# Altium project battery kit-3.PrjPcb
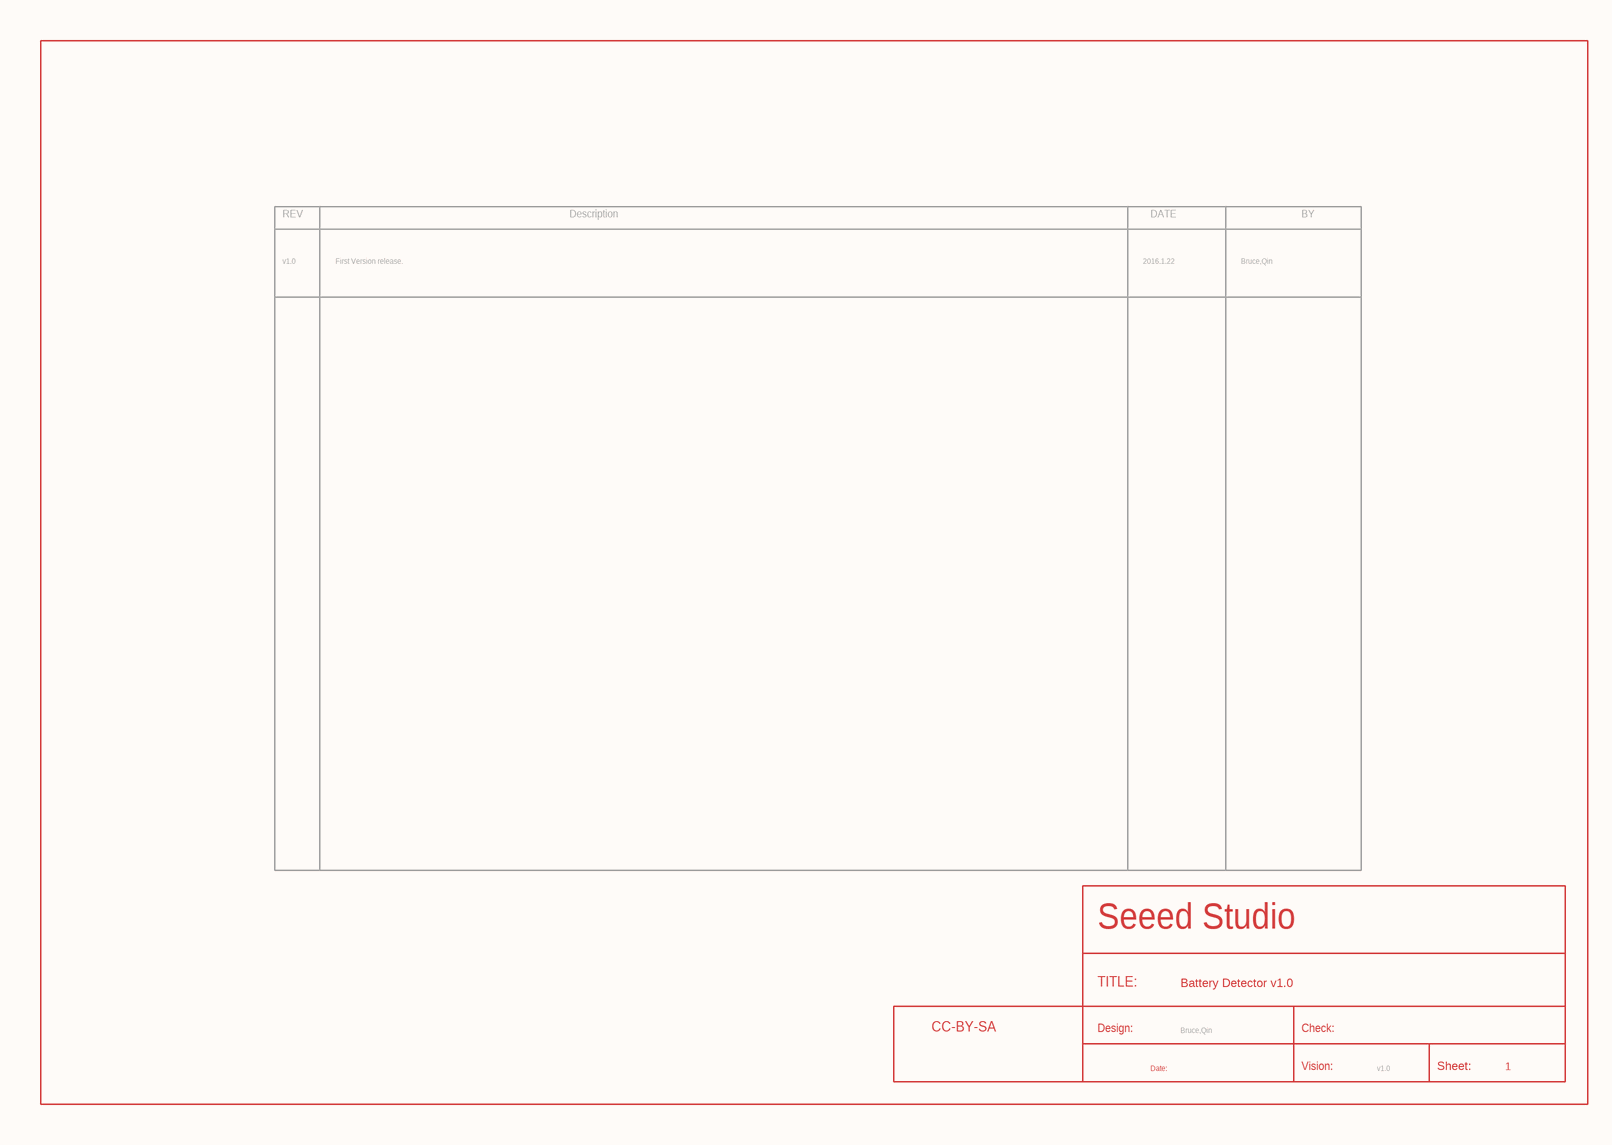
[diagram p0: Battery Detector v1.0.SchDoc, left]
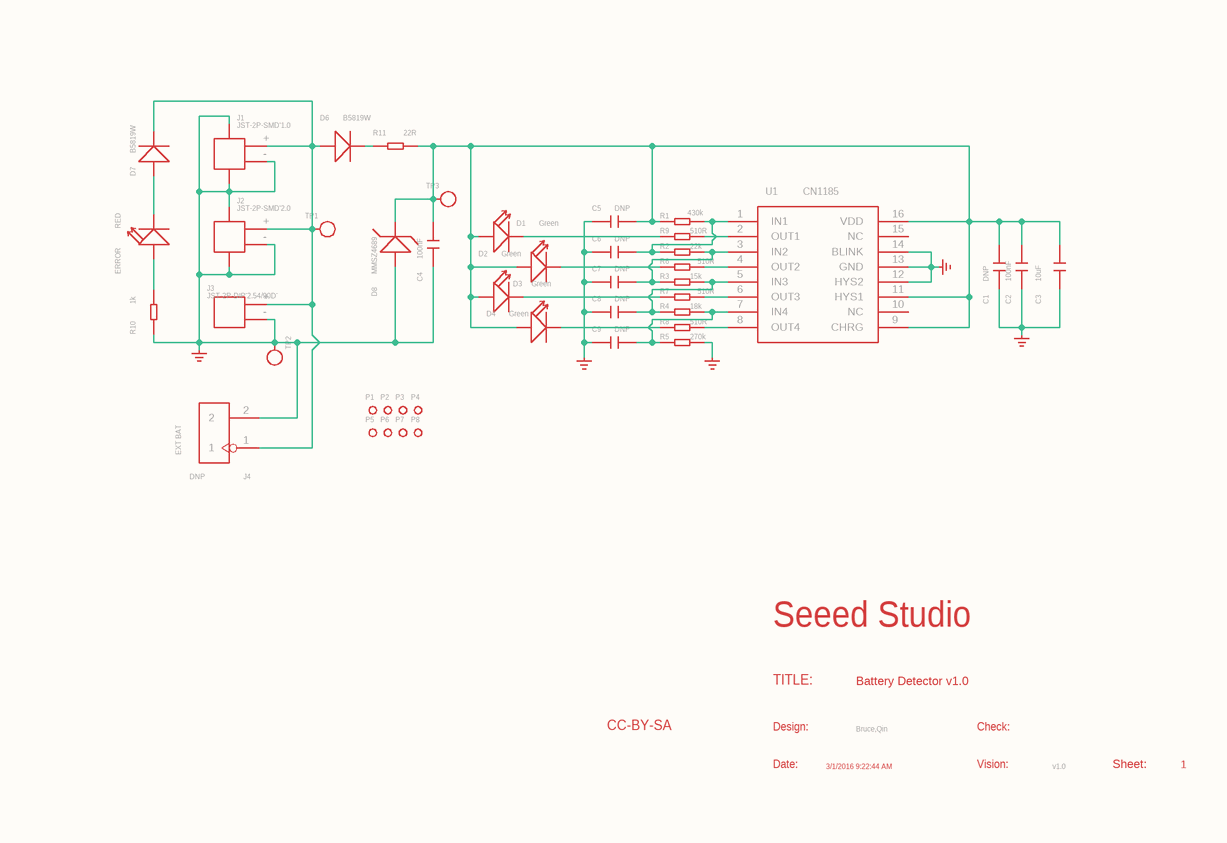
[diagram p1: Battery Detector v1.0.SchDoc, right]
1 sheet, 51 parts. Net scope: global (net labels, ports and power ports of the same name join across sheets).
Board file: Battery Detector v1.0.PcbDoc

## Sheet Battery Detector v1.0.SchDoc: Battery Detector v1.0
size 545 x 197 mm; Date: 3/1/2016 9:22:44 AM; SheetNumber: 1; Origin: Eagle; GateName_1: G$1; SymbolName_1: SEEEDSTUDIO-OPEN-SCH-FRAME; LibraryName: moudle-new; DeviceSetName: SEEEDSTUDIO-OPEN-SCH-FRAME; Sheet: Sheet:; SeeedStudio: Seeed Studio; Design: Design:; Check: Check:; Vision: Vision:; CC-BY-SA: CC-BY-SA

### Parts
C1  DNP  [C0603]
C2  100nF  [C0603]
C3  10uF  [C0805]
C4  100nF  [C0603]
C5  DNP  [C0603]
C6  DNP  [C0603]
C7  DNP  [C0603]
C8  DNP  [C0603]
C9  DNP  [C0603]
D1  Green  [LED-0603]
D2  Green  [LED-0603]
D3  Green  [LED-0603]
D4  Green  [LED-0603]
D6  B5819W  [SOD-123]
D7  B5819W  [SOD-123]
D8  MMSZ4689  [SOD-123]
ERROR  RED  [LED-0603]
FR2  DRAWING_NAME: Battery Detector v1.0  SHEET: 1  Sheet: Sheet:  SeeedStudio: Seeed Studio  TITLE: TITLE:  Design: Design:  Check: Check:  Vision: Vision:  Date: Date:  [SEEEDSTUDIO-PCB-FRAME]  (hidden comment: SEEEDSTUDIO-OPEN-SCH-FRAME)
J1  JST-2P-SMD'1.0  [HW2-SMD-1.0-90D]
J2  JST-2P-SMD'2.0  [HW2-SMD-2.0-90D]
J3  JST-2P-DIP'2.54/90D'  [JST2-2.54-90D]
J4  DNP  [H2-2.54]
P1  MARK-1.0'ANNULAR'  [ROUND-MARK-1.0]  (value not drawn)
P2  MARK-1.0'ANNULAR'  [ROUND-MARK-1.0]  (value not drawn)
P3  MARK-1.0'ANNULAR'  [ROUND-MARK-1.0]  (value not drawn)
P4  MARK-1.0'ANNULAR'  [ROUND-MARK-1.0]  (value not drawn)
P5  MARK-1.0'ANNULAR'  [ROUND-MARK-1.0]  (value not drawn)
P6  MARK-1.0'ANNULAR'  [ROUND-MARK-1.0]  (value not drawn)
P7  MARK-1.0'ANNULAR'  [ROUND-MARK-1.0]  (value not drawn)
P8  MARK-1.0'ANNULAR'  [ROUND-MARK-1.0]  (value not drawn)
R1  430k  [R0603]
R2  22k  [R0603]
R3  15k  [R0603]
R4  18k  [R0603]
R5  270k  [R0603]
R6  510R  [R0603]
R7  510R  [R0603]
R8  510R  [R0603]
R9  510R  [R0603]
R10  1k  [R0603]
R11  22R  [R0805]
TP1  DNP  [TP-D45MIL]  (value not drawn)
TP2  DNP  [TP-D45MIL]  (value not drawn)
TP3  DNP  [TP-D45MIL]  (value not drawn)
U1  CN1185  [TSSOP16-0.65-5X4.4MM]
U$1  SEEEDSTUDIO-SCH-MODLIST  (value not drawn)
U$2  GND_POWER  (value not drawn)
U$3  GND_POWER  (value not drawn)
U$4  GND_POWER  (value not drawn)
U$5  GND_POWER  (value not drawn)
U$6  GND_POWER  (value not drawn)

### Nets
NetC1_1: C1.1 C2.1 C3.2 U$4.?1(GND)
NetC1_2: C1.2 C2.2 C3.1 C4.2 C5.2 D1.+ D2.+ D3.+ D4.+ D8.- R1.2 R11.1 TP3.T U1.9(CHRG) U1.11(HYS1) U1.16(VDD)
NetC4_1: C4.1 D6.+ D7.- D8.+ J1.3 J1.4 J1.+ J1.- J2.3 J2.4 J2.+ J2.- J3.+(P$1) J3.-(P$2) J4.1 J4.2 R10.2 TP1.T TP2.T U$5.?1(GND)
NetC5_1: C5.1 C6.1 C7.1 C8.1 C9.1 U$6.?1(GND)
NetC6_2: C6.2 R1.1 R2.2 R9.1 U1.1(IN1) U1.2(OUT1)
NetC7_2: C7.2 D2.- R2.1 R3.2 R6.2 U1.3(IN2)
NetC8_2: C8.2 D3.- R3.1 R4.2 R7.2 U1.5(IN3)
NetC9_2: C9.2 D4.- R4.1 R5.2 R8.2 U1.7(IN4)
NetD1_-: D1.- R9.2
NetD6_-: D6.- R11.2
NetD7_+: D7.+ ERROR.-
NetERROR_+: ERROR.+ R10.1
NetR5_1: R5.1 U$3.?1(GND)
NetR6_1: R6.1 U1.4(OUT2)
NetR7_1: R7.1 U1.6(OUT3)
NetR8_1: R8.1 U1.8(OUT4)
NetU1_12: U1.12(HYS2) U1.13(GND) U1.14(BLINK) U$2.?1(GND)

Not connected (* = marked no-connect by the designer): U1 10(NC) 15(NC)

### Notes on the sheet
- (near U$1) v1.0
- First Version release.
- 2016.1.22
- Bruce,Qin
- (near J4) EXT BAT
- Seeed Studio
- CC-BY-SA
- TITLE:
- Design:
- Battery Detector v1.0
- Check:
- v1.0
- Date:
- 3/1/2016 9:22:44 AM
- Vision:
- Sheet:
- 1

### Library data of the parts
C1 C2 C4-C9 = CAP-0603: Ceramic Capacitors; GateName_1: C; DeviceName: -0603; DeviceSetName: CAP
C3 = CAP-0805: Ceramic Capacitors; GateName_1: C; DeviceName: -0805; DeviceSetName: CAP
D1-D4 ERROR = LED'0603': GateName_1: LED; DeviceName: '0603'
D6 D7 = DIODE*'1206': GateName_1: D; SymbolName_1: DIODE*; DeviceName: '1206'
D8 = D-ZENER-2P'MMSZ4689-V': SOD-123:304030008;SOT-23:304030000; GateName_1: G$1
FR2 = SEEEDSTUDIO-OPEN-SCH-FRAME: GateName_1: G$1
J1 = JST-2P-SMD'1.0': 2P-SMD-1.0-90D:320110054;2P-SMD-2.0-90D:320110026; GateName_1: G$1; DeviceName: '1.0'
J2 = JST-2P-SMD'2.0': 2P-SMD-1.0-90D:320110054;2P-SMD-2.0-90D:320110026; GateName_1: G$1; DeviceName: '2.0'
J3 = JST-2P-DIP'2.54/90D': 2P-2.0:320110049;2P-2.0-90D:320110027;2P-2.54:320110053;2P-2.54-90D:320110000; GateName_1: G$1
J4 = HEADER-2P-65/35MIL: GateName_1: G$1
P1-P8 = MARK-1.0'ANNULAR': PARTNO: DNP; GateName_1: G$1
R1-R10 = RES-0603: GateName_1: R; SymbolName_1: RES-ARRAY; DeviceName: -0603; DeviceSetName: RES
R11 = RES-0805: GateName_1: R; SymbolName_1: RES-ARRAY; DeviceName: -0805; DeviceSetName: RES
TP1-TP3 = TEST-POINT'4545': GateName_1: TP; DeviceName: '4545'
U1 = CN1185: ä½ŽåŠŸè€—å››é€šé“ç”µåŽ‹æ£€æµ‹é›†æˆç”µè·¯; GateName_1: G$1
U$1 = SEEEDSTUDIO-SCH-MODLIST: GateName_1: G$1; SymbolName_1: SEEDSTUDIO-SCH-MODLIST
U$2-U$6 = GND_POWER: GateName_1: G$1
